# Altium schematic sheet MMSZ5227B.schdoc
size 127 x 101 mm
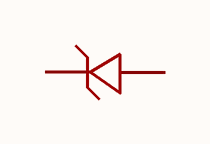
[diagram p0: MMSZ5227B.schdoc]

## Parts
ZD?  mmsz5227b  [SOD-123_L2.8-W1.8-LS3.7-RD]  (value not drawn)

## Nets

Not connected (* = marked no-connect by the designer): ZD? 1(K) 2(A)

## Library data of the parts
ZD? = mmsz5227b: 二极管配置:1个独立式;稳压值(标称值):3.6V;稳压值(范围值):3.42V~3.78V;耗散功率(Pd):350mW;; Manufacturer: CJ(江苏长电/长晶); AddInBom: yes; ModelId: 7884390a25fb4c08947731ebfba7e3f8; ModelTransform: 144.8816,62.992,0,0,0,0,0,0,0; Diode Configuration: 1个独立式; Zener Voltage(Nom): 3.6V; Reverse Leakage Current (Ir): 15uA@1V; Pd - Power Dissipation: 350mW; Impedance(Zzt): 24Ω; Impedance(Zzk): 1.7kΩ; Operating Junction Temperature Range: -65℃~+150℃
